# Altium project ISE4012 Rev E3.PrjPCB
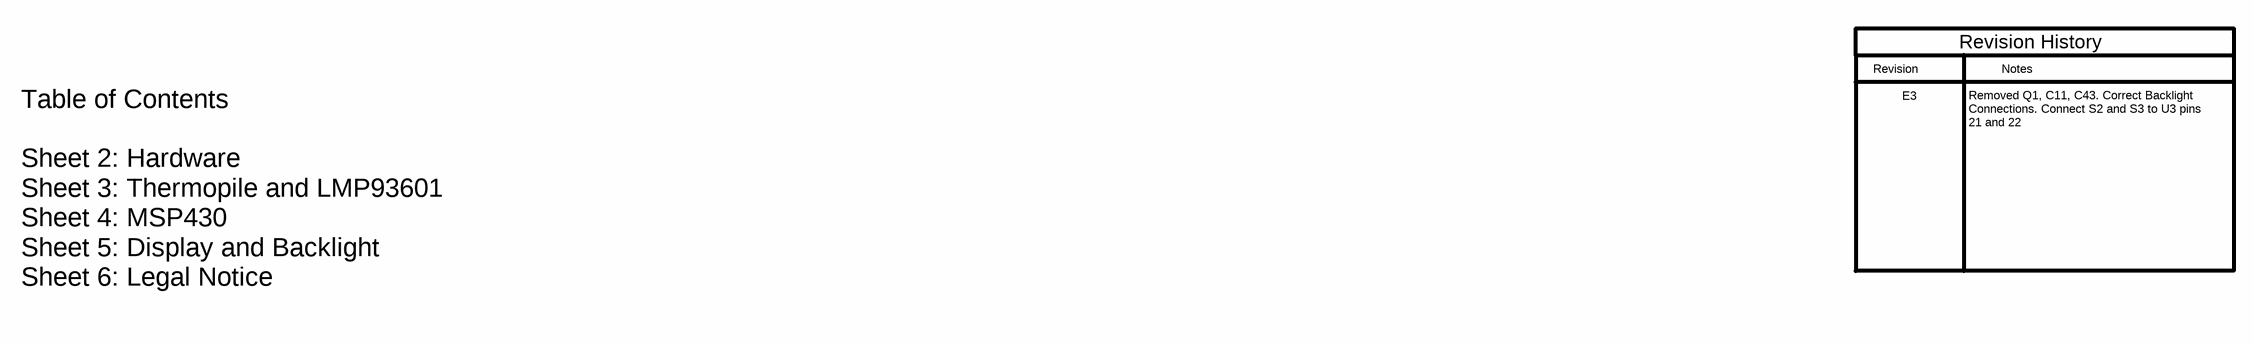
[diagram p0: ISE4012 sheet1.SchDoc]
TechSupport: http://www.ti.com/support; SCH_Rev: E3; PRJ_Title: TIDA-00211 Thermopile Hand Gesture Backlight Controller; PRJ_Number: ISE4012; PRJ_Engineer: M. Knapp; PRJ_Customer: Public Release; PCB_Rev: E3; PCB_Layout: Krypton Solution LLC; CopyrightYear: 2014
6 sheets, 145 parts. Net scope: global (net labels, ports and power ports of the same name join across sheets).
Board file: ISE4012 RevE3.PcbDoc
Sheets:
  ISE4012 sheet1.SchDoc
  ISE4012 sheet2.SchDoc
  ISE4012 sheet3.SchDoc
  ISE4012 sheet4.SchDoc
  ISE4012 sheet5.SchDoc
  ISE4012 Sheet 6.SchDoc

## Sheet ISE4012 sheet1.SchDoc
size 431 x 279 mm; Date: Not shown in title block; ApprovedBy: Not shown in title block; CheckedBy: Not shown in title block; Author: Not shown in title block; CompanyName: Not shown in title block; Engineer: Not shown in title block; Organization: Not shown in title block; Address1: Not shown in title block; Address2: Not shown in title block; Address3: Not shown in title block; Address4: Not shown in title block; DocumentNumber: 1; Revision: Use project parameter SCH_Rev; SheetNumber: 1; SheetTotal: 6; PageSetup: Record=PageOptions|CenterHorizontal=True|CenterVertical=True|PrintScale=1.00|XCorrection=1.00|YCorrection=1.00|PrintKind=0|BorderSize=5000000|LeftOffset=0|BottomOffset=0|Orientation=2|PaperLength=1000|PaperWidth=1000|Scale=100|PaperSource=15|PrintQuality=600|MediaType=1|DitherType=10|PaperKind=Letter|PrintScaleMode=1

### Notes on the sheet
- Revision
- E3
- Notes
- Revision History
- Removed Q1, C11, C43. Correct Backlight Connections. Connect S2 and S3 to U3 pins 21 and 22
- Table of Contents
  Sheet 2: Hardware
  Sheet 3: Thermopile and LMP93601
  Sheet 4: MSP430
  Sheet 5: Display and Backlight
  Sheet 6: Legal Notice

## Sheet ISE4012 sheet2.SchDoc
size 431 x 279 mm; Date: Not shown in title block; ApprovedBy: Not shown in title block; CheckedBy: Not shown in title block; Author: Not shown in title block; CompanyName: Not shown in title block; Engineer: Not shown in title block; Organization: Not shown in title block; Address1: Not shown in title block; Address2: Not shown in title block; Address3: Not shown in title block; Address4: Not shown in title block; DocumentNumber: 2; Revision: Use project parameter SCH_Rev; SheetNumber: 2; SheetTotal: 6; PageSetup: Record=PageOptions|CenterHorizontal=True|CenterVertical=True|PrintScale=1.00|XCorrection=1.00|YCorrection=1.00|PrintKind=0|BorderSize=5000000|LeftOffset=0|BottomOffset=0|Orientation=2|PaperLength=1000|PaperWidth=1000|Scale=100|PaperSource=15|PrintQuality=600|MediaType=1|DitherType=10|PaperKind=Letter|PrintScaleMode=1
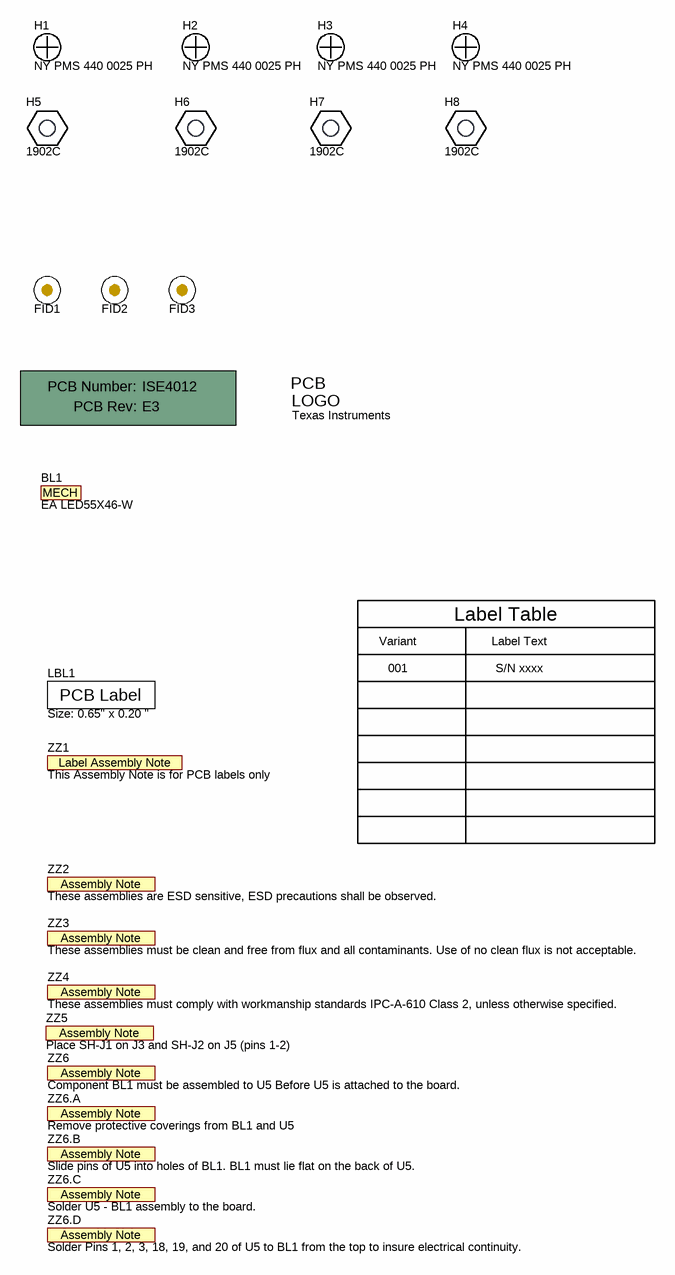
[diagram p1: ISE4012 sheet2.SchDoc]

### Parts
!PCB  Printed Circuit Board  (value not drawn)  (mechanical)
BL1  EA LED55X46-W  (mechanical)
FID1  Fiducial  [Fiducial10-20]  (value not drawn)
FID2  Fiducial  [Fiducial10-20]  (value not drawn)
FID3  Fiducial  [Fiducial10-20]  (value not drawn)
H1  NY PMS 440 0025 PH  [NY PMS 440 0025 PH]
H2  NY PMS 440 0025 PH  [NY PMS 440 0025 PH]
H3  NY PMS 440 0025 PH  [NY PMS 440 0025 PH]
H4  NY PMS 440 0025 PH  [NY PMS 440 0025 PH]
H5  1902C  [Keystone_1902C]
H6  1902C  [Keystone_1902C]
H7  1902C  [Keystone_1902C]
H8  1902C  [Keystone_1902C]
LBL1  Size: 0.65" x 0.20 "  [Label_650x200]
Logo1  Texas Instruments  [TI_Stacked_Overlay_Medium]  (no BOM)
ZZ1  This Assembly Note is for PCB labels only  [AssemblyNoteLabel]  (no BOM)
ZZ2  These assemblies are ESD sensitive, ESD precautions shall be observed.  [AssemblyNote]  (no BOM)
ZZ3  These assemblies must be clean and free from flux and all contaminants. Use of no clean flux is not acceptable.  [AssemblyNote]  (no BOM)
ZZ4  These assemblies must comply with workmanship standards IPC-A-610 Class 2, unless otherwise specified.  [AssemblyNote]  (no BOM)
ZZ5  Place SH-J1 on J3 and SH-J2 on J5 (pins 1-2)  [AssemblyNote]  (no BOM)
ZZ6  Component BL1 must be assembled to U5 Before U5 is attached to the board.  [AssemblyNote]  (no BOM)
ZZ6.A  Remove protective coverings from BL1 and U5  [AssemblyNote]  (no BOM)
ZZ6.B  Slide pins of U5 into holes of BL1. BL1 must lie flat on the back of U5.  [AssemblyNote]  (no BOM)
ZZ6.C  Solder U5 - BL1 assembly to the board.  [AssemblyNote]  (no BOM)
ZZ6.D  Solder Pins 1, 2, 3, 18, 19, and 20 of U5 to BL1 from the top to insure electrical continuity.  [AssemblyNote]  (no BOM)

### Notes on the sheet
- Variant
- Label Table
- Label Text
- 001
- S/N xxxx

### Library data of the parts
!PCB = PCB: Manufacturer: Any; PartNumber: ISE4012; SymbolCreator: a0412235
BL1 = EA LED55X46-W: LED Backlight, White; Manufacturer: Electronic Assembly; SymbolCreator: codlsc
FID1-FID3 = Fiducial: Fiducial mark.  There is nothing to buy or mount.; SymbolCreator: codlsc
H1-H4 = NY PMS 440 0025 PH: Machine Screw, Round, #4-40 x 1/4, Nylon, Philips panhead; Manufacturer: B&F Fastener Supply; CompType: Hardware; SymbolCreator: codlsc; U/M: EA
H5-H8 = 1902C: Standoff, Hex, 0.5"L #4-40 Nylon; Manufacturer: Keystone; CompType: Hardware
LBL1 = THT-14-423-10: Thermal Transfer Printable Labels, 0.650" W x 0.200" H - 10,000 per roll; Manufacturer: Brady; SymbolCreator: a0412235; CompType: Label
Logo1 = TI_Logo: Texas Instrument Corporate Signature; SymbolCreator: a0412235
ZZ1 = AssemblyNoteLabel: SymbolCreator: a0412235
ZZ2-ZZ6 ZZ6.A ZZ6.B ZZ6.C ZZ6.D = AssemblyNote: SymbolCreator: codlsc

## Sheet ISE4012 sheet3.SchDoc
size 431 x 279 mm; Date: Not shown in title block; ApprovedBy: Not shown in title block; CheckedBy: Not shown in title block; Author: Not shown in title block; CompanyName: Not shown in title block; Engineer: Not shown in title block; Organization: Not shown in title block; Address1: Not shown in title block; Address2: Not shown in title block; Address3: Not shown in title block; Address4: Not shown in title block; DocumentNumber: 3; Revision: Use project parameter SCH_Rev; SheetNumber: 3; SheetTotal: 6; PageSetup: Record=PageOptions|CenterHorizontal=True|CenterVertical=True|PrintScale=0.96|XCorrection=1.00|YCorrection=1.00|PrintKind=0|BorderSize=5000000|LeftOffset=0|BottomOffset=0|Orientation=2|PaperLength=4318|PaperWidth=2794|Scale=100|PaperSource=15|PrintQuality=600|MediaType=1|DitherType=10|PaperKind=11x17|PrintScaleMode=1
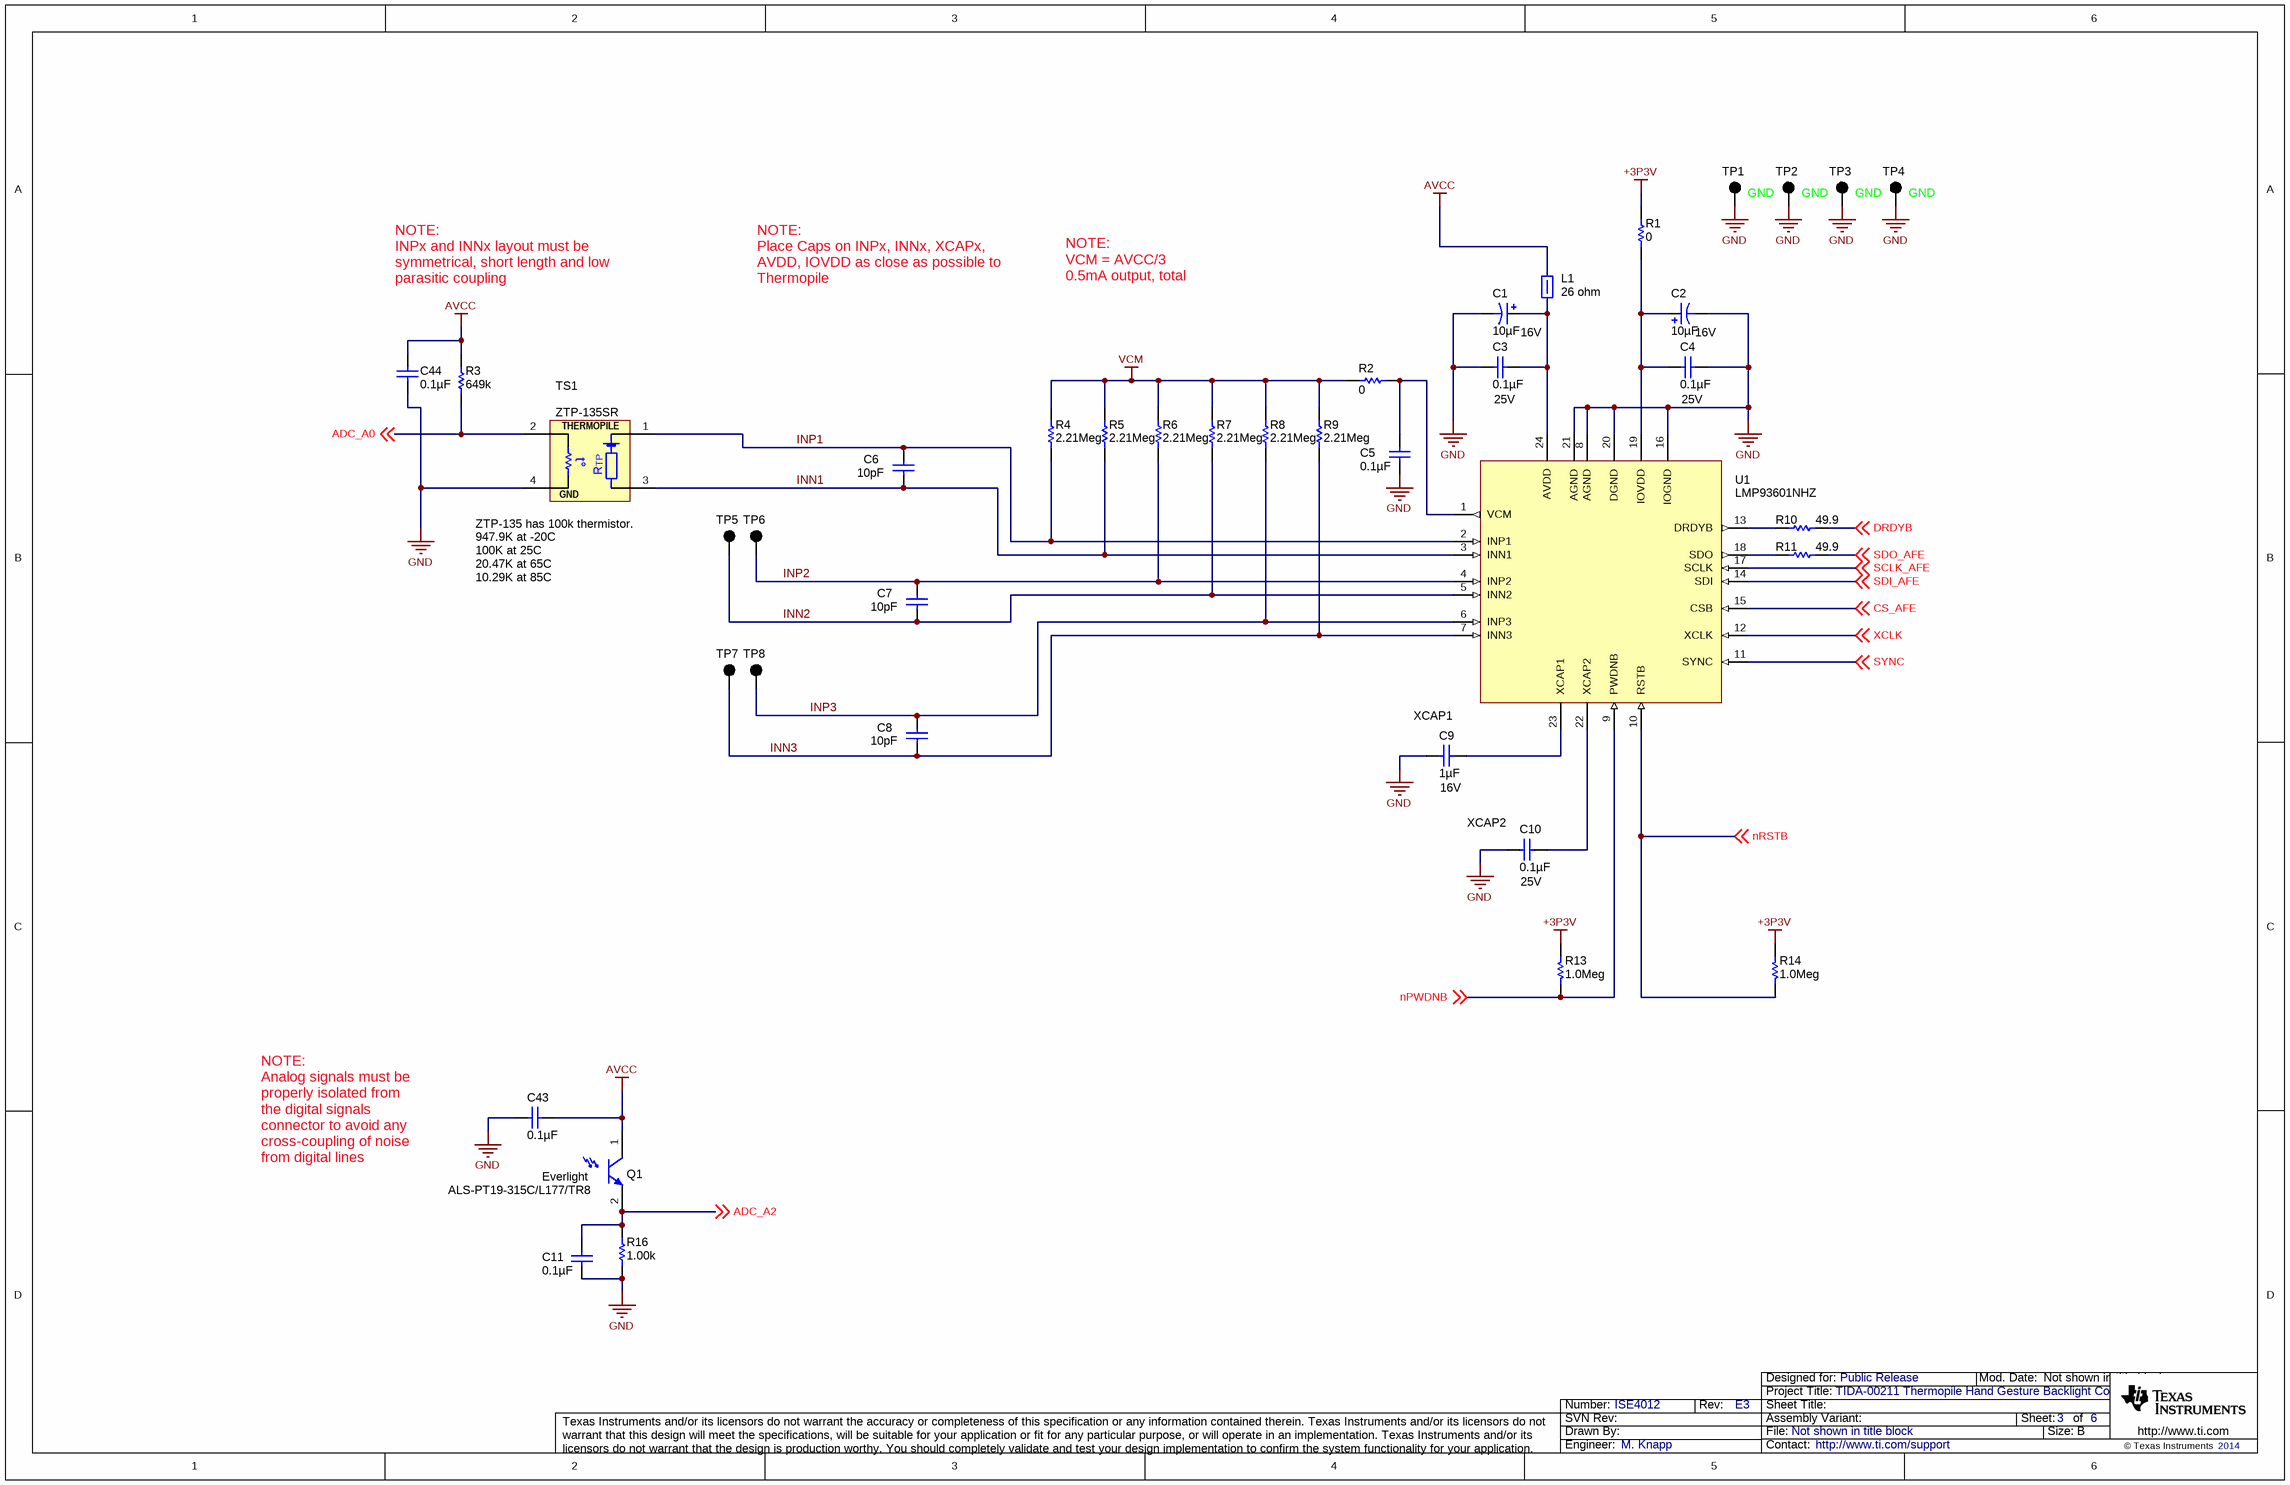
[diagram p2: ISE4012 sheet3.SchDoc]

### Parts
C1  ValueDisplayed: 10µF  Value2: 16V  [3528-21]  (hidden comment: TPSB106K016R0800)
C2  ValueDisplayed: 10µF  Value2: 16V  [3528-21]  (hidden comment: TPSB106K016R0800)
C3  ValueDisplayed: 0.1µF  Value2: 25V  [0603]  (hidden comment: 06033C104JAT2A)
C4  ValueDisplayed: 0.1µF  Value2: 25V  [0603]  (hidden comment: 06033C104JAT2A)
C5  ValueDisplayed: 0.1µF  [0603]  (hidden comment: 06033C104JAT2A)
C6  ValueDisplayed: 10pF  [0603]  (hidden comment: 06033C104JAT2A)
C7  ValueDisplayed: 10pF  [0603]  (hidden comment: 06033C104JAT2A)
C8  ValueDisplayed: 10pF  [0603]  (hidden comment: 06033C104JAT2A)
C9  ValueDisplayed: 1µF  Value2: 16V  [0603]  (hidden comment: C1608X7R1C105K)
C10  ValueDisplayed: 0.1µF  Value2: 25V  [0603]  (hidden comment: 06033C104JAT2A)
C11  ValueDisplayed: 0.1µF  [0603]  (hidden comment: 06033C104JAT2A)
C43  ValueDisplayed: 0.1µF  [0603]  (hidden comment: 06033C104JAT2A)
C44  ValueDisplayed: 0.1µF  [0603]  (hidden comment: 06033C104JAT2A)
L1  value 26 ohm  [0603]  (hidden comment: BLM18SG260TN1D)
Q1  Manufacturer: Everlight  [ALS-PT19-315C-L177-TR8]  (hidden comment: ALS-PT19-315C/L177/TR8)
R1  value 0  [0603]  (hidden comment: CRCW06030000Z0EA)
R2  value 0  [0603]  (hidden comment: CRCW06030000Z0EA)
R3  value 649k  [0603]  (hidden comment: CRCW0603649KFKEA)
R4  value 2.21Meg  [0603]  (hidden comment: RC0603FR-072M21L)
R5  value 2.21Meg  [0603]  (hidden comment: RC0603FR-072M21L)
R6  value 2.21Meg  [0603]  (hidden comment: RC0603FR-072M21L)
R7  value 2.21Meg  [0603]  (hidden comment: RC0603FR-072M21L)
R8  value 2.21Meg  [0603]  (hidden comment: RC0603FR-072M21L)
R9  value 2.21Meg  [0603]  (hidden comment: RC0603FR-072M21L)
R10  value 49.9  [0603]  (hidden comment: CRCW060349R9FKEA)
R11  value 49.9  [0603]  (hidden comment: CRCW060349R9FKEA)
R13  value 1.0Meg  [0603]  (hidden comment: CRCW06031M00JNEA)
R14  value 1.0Meg  [0603]  (hidden comment: CRCW06031M00JNEA)
R16  value 1.00k  [0603]  (hidden comment: CRCW06031K00FKEA)
TP1  5000  [Keystone5000]  (value not drawn)
TP2  5000  [Keystone5000]  (value not drawn)
TP3  5000  [Keystone5000]  (value not drawn)
TP4  5000  [Keystone5000]  (value not drawn)
TP5  5001  [Keystone5001]  (value not drawn)
TP6  5001  [Keystone5001]  (value not drawn)
TP7  5001  [Keystone5001]  (value not drawn)
TP8  5001  [Keystone5001]  (value not drawn)
TS1  ZTP-135SR  [TO-46]
U1  LMP93601NHZ  [NHZ0024B]

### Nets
+3P3V: R1.2 R13.2 R14.2
AVCC: C43.1 C44.1 L1.2 Q1.1(C) R3.2
GND: C1.2(-) C2.2(-) C3.2 C4.1 C5.2 C9.2 C10.2 C11.2 C43.2 C44.2 R16.1 TP1.1 TP2.1 TP3.1 TP4.1 TS1.4(IN) U1.8(AGND) U1.16(IOGND) U1.20(DGND) U1.21(AGND)
VCM: R2.1 R4.2 R5.2 R6.2 R7.2 R8.2 R9.2
ADC_A0: R3.1 TS1.2(IN) ; off-sheet ADC_A0
ADC_A2: C11.1 Q1.2(E) R16.2 ; off-sheet ADC_A2
CS_AFE: U1.15(CSB) ; off-sheet CS_AFE
DRDYB: R10.2 ; off-sheet DRDYB
INN1: C6.2 R5.1 TS1.3(OUT) U1.3(INN1)
INN2: C7.2 R7.1 TP5.1 U1.5(INN2)
INN3: C8.2 R9.1 TP7.1 U1.7(INN3)
INP1: C6.1 R4.1 TS1.1(OUT) U1.2(INP1)
INP2: C7.1 R6.1 TP6.1 U1.4(INP2)
INP3: C8.1 R8.1 TP8.1 U1.6(INP3)
nPWDNB: R13.1 U1.9(PWDNB) ; off-sheet nPWDNB
nRSTB: R14.1 U1.10(RSTB) ; off-sheet nRSTB
SCLK_AFE: U1.17(SCLK) ; off-sheet SCLK_AFE
SDI_AFE: U1.14(SDI) ; off-sheet SDI_AFE
SDO_AFE: R11.2 ; off-sheet SDO_AFE
SYNC: U1.11(SYNC) ; off-sheet SYNC
XCLK: U1.12(XCLK) ; off-sheet XCLK
NetC1_1: C1.1(+) C3.1 L1.1 U1.24(AVDD)
NetC2_1: C2.1(+) C4.2 R1.1 U1.19(IOVDD)
NetC5_1: C5.1 R2.2 U1.1(VCM)
NetC9_1: C9.1 U1.23(XCAP1)
NetC10_1: C10.1 U1.22(XCAP2)
NetR10_1: R10.1 U1.13(DRDYB)
NetR11_1: R11.1 U1.18(SDO)

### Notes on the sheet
- GND
- (near TP4) GND
- NOTE:
  INPx and INNx layout must be symmetrical, short length and low parasitic coupling
- NOTE:
  Place Caps on INPx, INNx, XCAPx, AVDD, IOVDD as close as possible to Thermopile
- NOTE:
  VCM = AVCC/3
  0.5mA output, total
- (near TS1) ZTP-135 has 100k thermistor.
  947.9K at -20C
  100K at 25C
  20.47K at 65C
  10.29K at 85C
- XCAP1
- (near C10) XCAP2
- NOTE:
  Analog signals must be properly isolated from the digital signals connector to avoid any cross-coupling of noise from digital lines

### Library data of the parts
C1 C2 = TPSB106K016R0800: CAP, TANT, 10uF, 16V, +/-10%, 0.8 ohm, 3528-21 SMD; Manufacturer: AVX; Polarized: Y; CompType: Capacitor; U/M: EA; Cap_F: 0.00001; Tolerance_%: 10; Value1: 0.8 ohm; VDC_V: 16; ESR_Ohm: 0.8; IRMS_A: 0.293; TaMin_C: -55; TaMax_C: 125; Cap_Case: B
C3-C5 C10 C11 C43 C44 = 06033C104JAT2A: CAP, CERM, 0.1uF, 25V, +/-5%, X7R, 0603; Manufacturer: AVX; Polarized: N; CompType: Capacitor; U/M: EA; Cap_F: 0.0000001; Tolerance_%: 5; ESR_Ohm: 0.05; Value1: 0.05 ohm; VDC_V: 25; TaMin_C: -55; TaMax_C: 125
C6-C8 = 06033C104JAT2A: CAP, CERM, 0.1uF, 25V, +/-5%, X7R, 0603; Manufacturer: AVX; ESR_Ohm: 0.05; Polarized: N; TaMax_C: 125; TaMin_C: -55; Tolerance_%: 5; VDC_V: 25; Cap_F: 0.0000001; CompType: Capacitor; U/M: EA; Value1: 0.05 ohm
C9 = C1608X7R1C105K: CAP, CERM, 1uF, 16V, +/-10%, X7R, 0603; Manufacturer: TDK; Polarized: N; CompType: Capacitor; U/M: EA; Cap_F: 0.000001; Tolerance_%: 10; ESR_Ohm: 0.0057; Value1: 0.0057 ohm; VDC_V: 16; TaMin_C: -55; TaMax_C: 125
L1 = BLM18SG260TN1D: 6A Ferrite Bead, 26 ohm @ 100MHz, SMD; Manufacturer: MuRata; Imax_A: 6; DCR_ohm: 0.007; Value1: 0.007 ohm; ZTyp@100MHz_Ohm: 26; U/M: EA
Q1 = ALS-PT19-315C/L177/TR8: AMBIENT LIGHT SENSOR, SMD; Symbol Creator: a0411947
R1 R2 = CRCW06030000Z0EA: RES, 0 ohm, 5%, 0.1W, 0603; Manufacturer: Vishay-Dale; CompType: Resistor; Value_Code: 0000; Tolerance_%: 5; Power_W: 0.1; VDC_V: 75; TempCo: 200 ppm/C; EIA_Code: E24; U/M: EA
R3 = CRCW0603649KFKEA: RES, 649k ohm, 1%, 0.1W, 0603; Manufacturer: Vishay-Dale; CompType: Resistor; Res_ohm: 649000; Tolerance_%: 1; Power_W: 0.1; VDC_V: 75; TempCo: 100 ppm/C; EIA_Code: E96; U/M: EA
R4-R9 = RC0603FR-072M21L: RES, 2.21Meg ohm, 1%, 0.1W, 0603; Manufacturer: Yageo America; CompType: Resistor; Res_ohm: 2210000; Value_Code: 2M21; Tolerance_%: 1; Power_W: 0.1; VDC_V: 150; TempCo: 200 ppm/C; EIA_Code: E96; U/M: EA
R10 R11 = CRCW060349R9FKEA: RES, 49.9 ohm, 1%, 0.1W, 0603; Manufacturer: Vishay-Dale; CompType: Resistor; Value_Code: 49R9; Tolerance_%: 1; Power_W: 0.1; VDC_V: 75; TempCo: 100 ppm/C; EIA_Code: E96; U/M: EA
R13 R14 = CRCW06031M00JNEA: RES, 1.0Meg ohm, 5%, 0.1W, 0603; Manufacturer: Vishay-Dale; CompType: Resistor; Tolerance_%: 5; VDC_V: 75; Power_W: 0.1; Res_ohm: 1000000; Value_Code: 1M00; TempCo_ppm/C: 200; EIA_Code: E24; U/M: EA
R16 = CRCW06031K00FKEA: RES, 1.00k ohm, 1%, 0.1W, 0603; Manufacturer: Vishay-Dale; CompType: Resistor; Res_ohm: 1000; Value_Code: 1k00; Tolerance_%: 1; Power_W: 0.1; VDC_V: 75; TempCo: 100 ppm/C; EIA_Code: E96; U/M: EA
TP1-TP8 = 5001: Test Point, Miniature, Black, TH; Manufacturer: Keystone; CompType: Test Point Loop; U/M: EA
TS1 = ZTP-135SR: Thermopile IR Sensor, TO-46; Manufacturer: Amphenol RF; SymbolCreator: a0799628
U1 = LMP93601NHZ: 16-bit analog-front-end for thermopile occupancy detector arrays, NHZ0024B; Alternate Manufacturer: None; Manufacturer: Texas Instruments; SymbolCreator: a0412235; CompType: IC; U/M: EA

## Sheet ISE4012 sheet4.SchDoc
size 431 x 279 mm; Date: Not shown in title block; ApprovedBy: Not shown in title block; CheckedBy: Not shown in title block; Author: Not shown in title block; CompanyName: Not shown in title block; Engineer: Not shown in title block; Organization: Not shown in title block; Address1: Not shown in title block; Address2: Not shown in title block; Address3: Not shown in title block; Address4: Not shown in title block; DocumentNumber: 4; Revision: Use project parameter SCH_Rev; SheetNumber: 4; SheetTotal: 6; PageSetup: Record=PageOptions|CenterHorizontal=True|CenterVertical=True|PrintScale=0.96|XCorrection=1.00|YCorrection=1.00|PrintKind=0|BorderSize=5000000|LeftOffset=0|BottomOffset=0|Orientation=2|PaperLength=4318|PaperWidth=2794|Scale=100|PaperSource=15|PrintQuality=600|MediaType=1|DitherType=10|PaperKind=11x17|PrintScaleMode=1
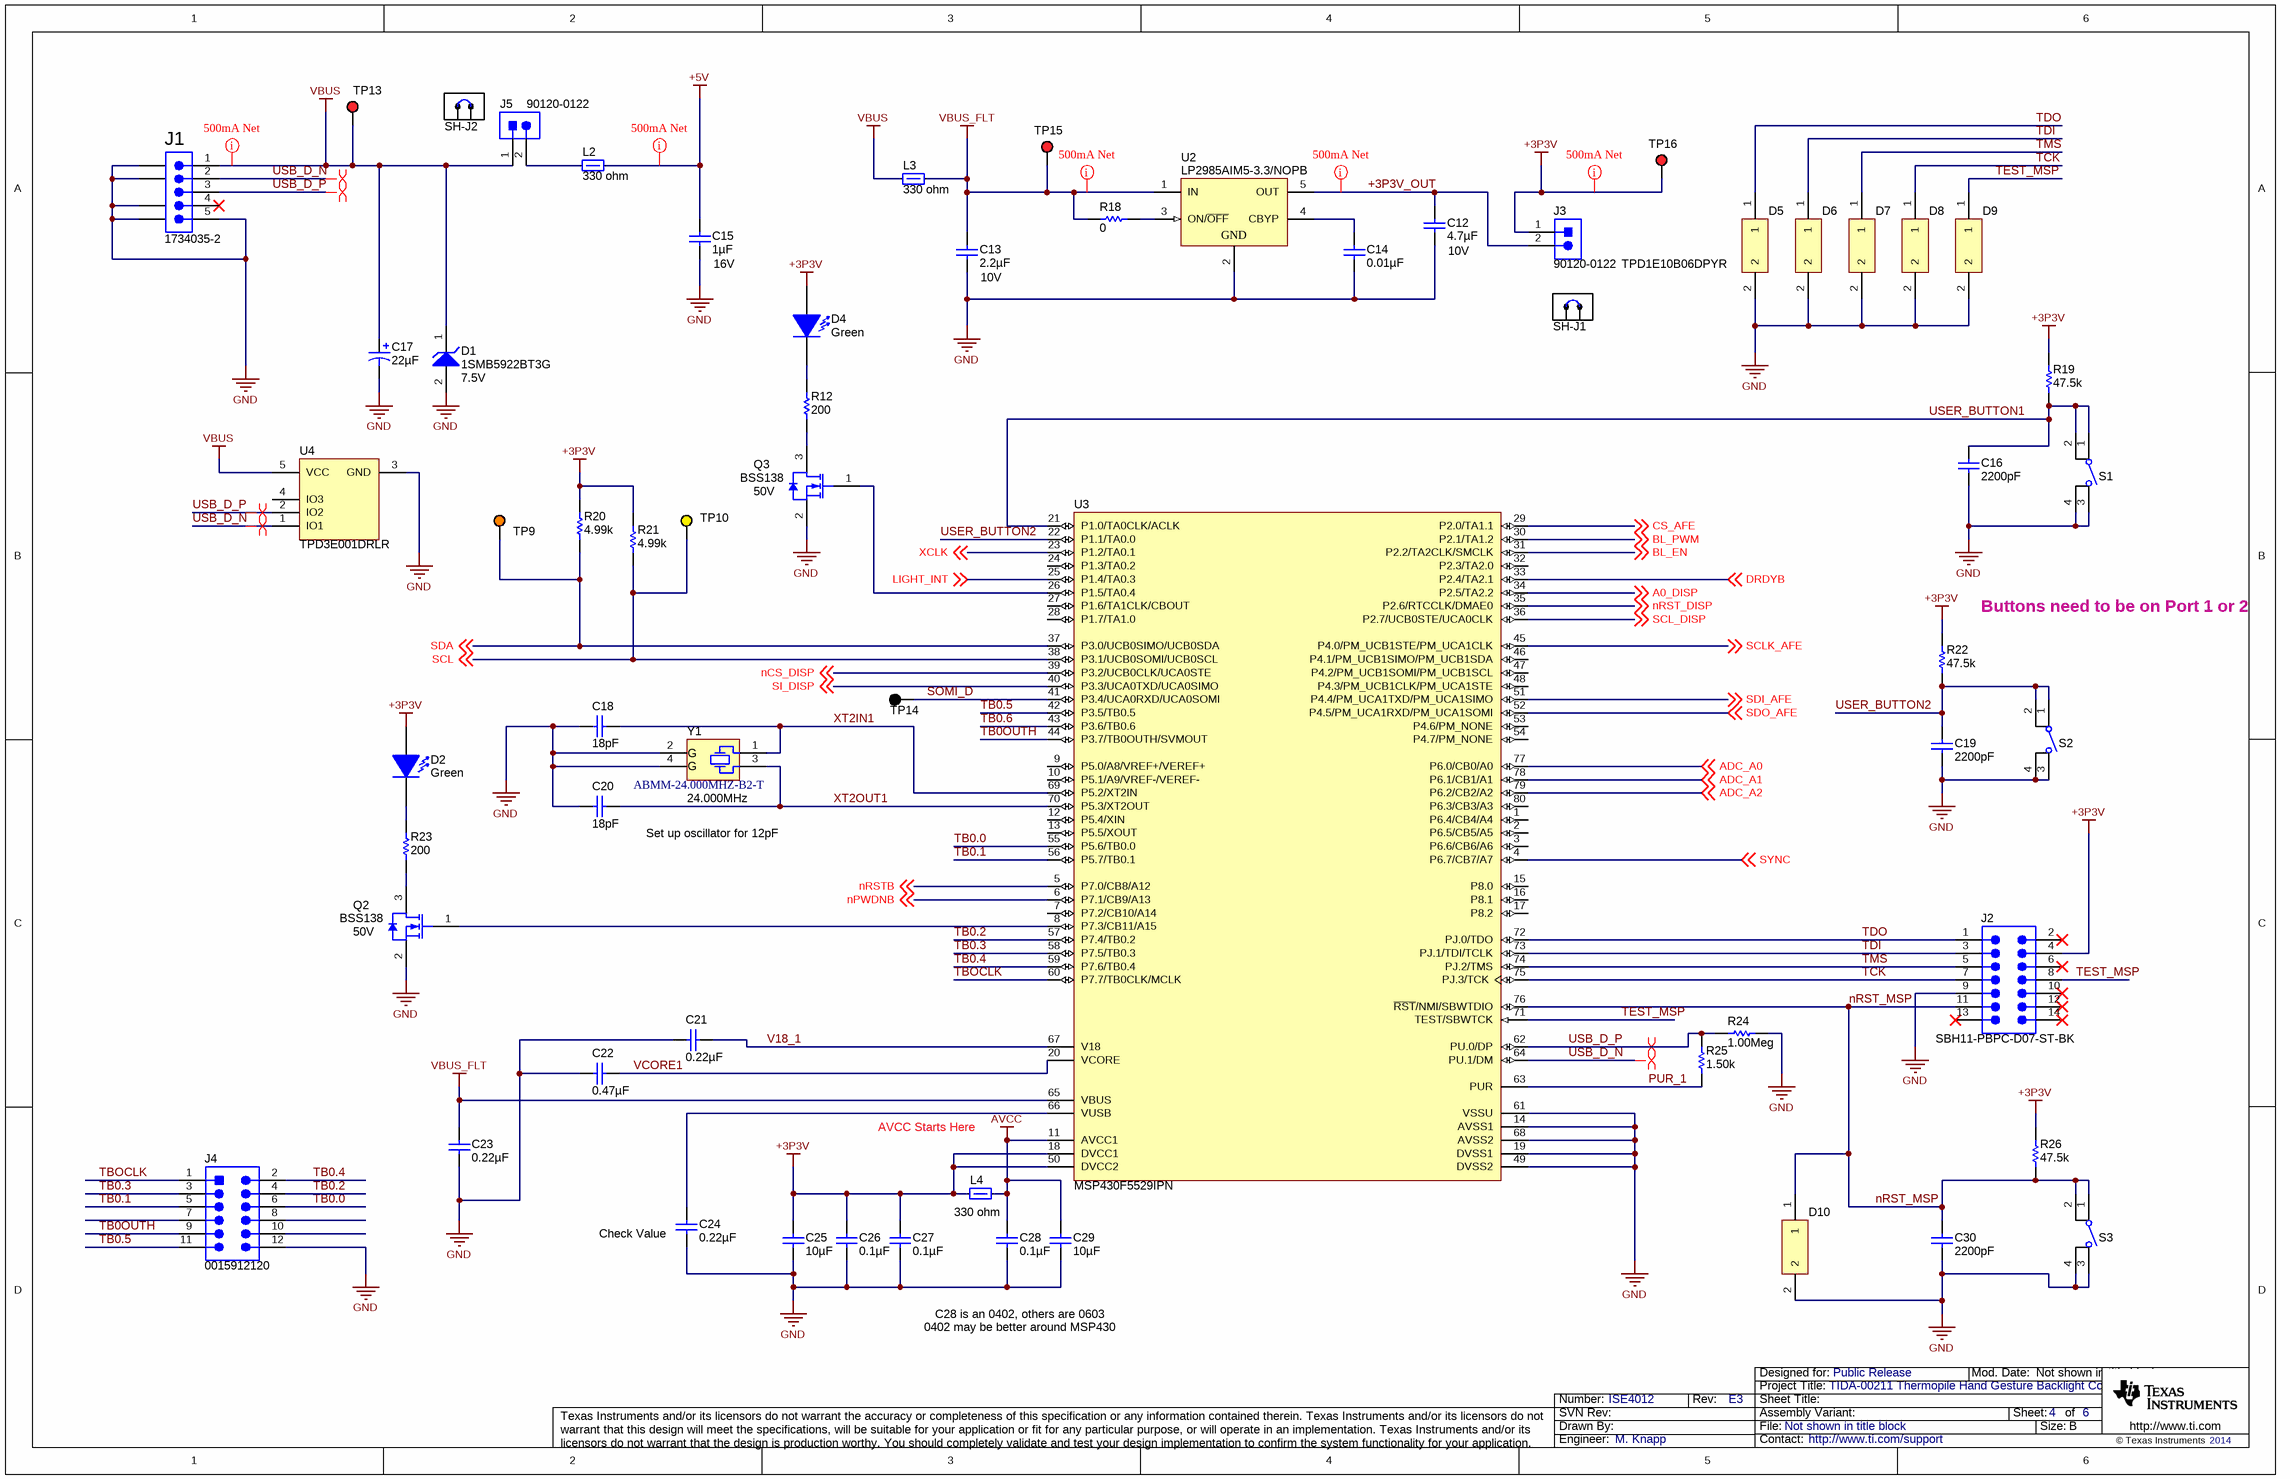
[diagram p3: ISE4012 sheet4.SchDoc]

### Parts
C12  ValueDisplayed: 4.7µF  Value2: 10V  [0805_HV]  (hidden comment: 0805ZD475KAT2A)
C13  ValueDisplayed: 2.2µF  Value2: 10V  [0805_HV]  (hidden comment: C0805C225K8PACTU)
C14  ValueDisplayed: 0.01µF  [0402]  (hidden comment: GRM155R71C103KA01D)
C15  ValueDisplayed: 1µF  Value2: 16V  [0603]  (hidden comment: C1608X7R1C105K)
C16  ValueDisplayed: 2200pF  [0603]  (hidden comment: 06031C222JAT2A)
C17  ValueDisplayed: 22µF  [CAPSMT_62_E55]  (hidden comment: EEE-1AA220WR)
C18  ValueDisplayed: 18pF  [0603]  (hidden comment: 06035A180JAT2A)
C19  ValueDisplayed: 2200pF  [0603]  (hidden comment: 06031C222JAT2A)
C20  ValueDisplayed: 18pF  [0603]  (hidden comment: 06035A180JAT2A)
C21  ValueDisplayed: 0.22µF  [0402]  (hidden comment: GRM155R61A224KE19D)
C22  ValueDisplayed: 0.47µF  [0402]  (hidden comment: GRM155R61A474KE15D)
C23  ValueDisplayed: 0.22µF  [0402]  (hidden comment: GRM155R61A224KE19D)
C24  ValueDisplayed: 0.22µF  [0402]  (hidden comment: GRM155R61A224KE19D)
C25  ValueDisplayed: 10µF  [0805_HV]  (hidden comment: C0805C106K8PACTU)
C26  ValueDisplayed: 0.1µF  [0603]  (hidden comment: 06033C104JAT2A)
C27  ValueDisplayed: 0.1µF  [0603]  (hidden comment: 06033C104JAT2A)
C28  ValueDisplayed: 0.1µF  [0402]  (hidden comment: GRM155R61C104KA88D)
C29  ValueDisplayed: 10µF  [0805_HV]  (hidden comment: C0805C106K8PACTU)
C30  ValueDisplayed: 2200pF  [0603]  (hidden comment: 06031C222JAT2A)
D1  1SMB5922BT3G  value 7.5V  [SMB]
D2  value Green  [LED_LTST-C171]  (hidden comment: LTST-C190GKT)
D4  value Green  [LED_LTST-C171]  (hidden comment: LTST-C190GKT)
D5  TPD1E10B06DPYR  [DPY0002A_N]
D6  TPD1E10B06DPYR  [DPY0002A_N]  (value not drawn)
D7  TPD1E10B06DPYR  [DPY0002A_N]  (value not drawn)
D8  TPD1E10B06DPYR  [DPY0002A_N]  (value not drawn)
D9  TPD1E10B06DPYR  [DPY0002A_N]  (value not drawn)
D10  TPD1E10B06DPYR  [DPY0002A_N]  (value not drawn)
J1  1734035-2  [CONN_USB-Mini-B-1734035-2]
J2  SBH11-PBPC-D07-ST-BK  [CONN_SBH11-PBPC-D07-ST-BK]
J3  90120-0122  [CONN_90120-0122]
J4  0015912120  [MOLEX_0015912120]
J5  90120-0122  [CONN_90120-0122]
L2  value 330 ohm  [0603]  (hidden comment: BLM18SG331TN1D)
L3  value 330 ohm  [0603]  (hidden comment: BLM18SG331TN1D)
L4  value 330 ohm  [0603]  (hidden comment: BLM18SG331TN1D)
Q2  BSS138  value 50V  [SOT-23]
Q3  BSS138  value 50V  [SOT-23]
R12  value 200  [0603]  (hidden comment: CRCW0603200RJNEA)
R18  value 0  [0402]  (hidden comment: CRCW04020000Z0ED)
R19  value 47.5k  [0603]  (hidden comment: CRCW060347K5FKEA)
R20  value 4.99k  [0402]  (hidden comment: CRCW04024K99FKED)
R21  value 4.99k  [0402]  (hidden comment: CRCW04024K99FKED)
R22  value 47.5k  [0603]  (hidden comment: CRCW060347K5FKEA)
R23  value 200  [0603]  (hidden comment: CRCW0603200RJNEA)
R24  value 1.00Meg  [0402L]  (hidden comment: CRCW04021M00FKED)
R25  value 1.50k  [0402L]  (hidden comment: CRCW04021K50FKED)
R26  value 47.5k  [0603]  (hidden comment: CRCW060347K5FKEA)
S1  4-1437565-1  [SW_FSM4JSMA]  (value not drawn)
S2  4-1437565-1  [SW_FSM4JSMA]  (value not drawn)
S3  4-1437565-1  [SW_FSM4JSMA]  (value not drawn)
SH-J1  2SN-BK-G  [2SN-BK-G]  (value not drawn)
SH-J2  2SN-BK-G  [2SN-BK-G]  (value not drawn)
TP9  5003  [Keystone5003]  (value not drawn)
TP10  5004  [Keystone5004]  (value not drawn)
TP13  5000  [Keystone5000]  (value not drawn)
TP14  5000  [Keystone5000]  (value not drawn)
TP15  5000  [Keystone5000]  (value not drawn)
TP16  5000  [Keystone5000]  (value not drawn)
U2  LP2985AIM5-3.3/NOPB  [MF05A_N]
U3  MSP430F5529IPN  [PN0080A_N]
U4  TPD3E001DRLR  [DRL0005A]
Y1  ABMM-24.000MHZ-B2-T  Frequency: 24.000MHz  [Abracon_ABMM]

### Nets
+3P3V: C25.1 C26.1 C27.1 D2.1(A) D4.1(A) J2.4 J3.1 L4.1 R19.2 R20.2 R21.2 R22.2 R26.2 TP16.1 U3.18(DVCC1) U3.50(DVCC2)
+5V: C15.1 L2.2
AVCC: C28.1 C29.1 L4.2 U3.11(AVCC1)
GND: C12.2 C13.2 C14.2 C15.2 C16.2 C17.2(-) C18.2 C19.2 C20.2 C21.2 C22.2 C23.2 C24.2 C25.2 C26.2 C27.2 C28.2 C29.2 C30.2 D1.2(A) D5.2 D6.2 D7.2 D8.2 D9.2 D10.2 J1.5 J1.6(GND) J1.7(GND) J1.8(GND) J1.9(GND) J2.9 J4.12 Q2.2(S) Q3.2(S) R24.2 S1.3 S1.4 S2.3 S2.4 S3.3 S3.4 U2.2(GND) U3.14(AVSS1) U3.19(DVSS1) U3.49(DVSS2) U3.61(VSSU) U3.68(AVSS2) U4.3(GND) Y1.2(GND) Y1.4(GND)
VBUS: C17.1(+) D1.1(K) J1.1 J5.1 L3.1 TP13.1 U4.5(VCC)
VBUS_FLT: C13.1 C23.1 L3.2 R18.2 TP15.1 U2.1(IN) U3.65(VBUS)
+3P3V_OUT: C12.1 J3.2 U2.5(OUT)
A0_DISP: U3.34(P2.5/TA2.2) ; off-sheet A0_DISP
ADC_A0: U3.77(P6.0/CB0/A0) ; off-sheet ADC_A0
ADC_A1: U3.78(P6.1/CB1/A1) ; off-sheet ADC_A1
ADC_A2: U3.79(P6.2/CB2/A2) ; off-sheet ADC_A2
BL_EN: U3.31(P2.2/TA2CLK/SMCLK) ; off-sheet BL_EN
BL_PWM: U3.30(P2.1/TA1.2) ; off-sheet BL_PWM
CS_AFE: U3.29(P2.0/TA1.1) ; off-sheet CS_AFE
DRDYB: U3.33(P2.4/TA2.1) ; off-sheet DRDYB
LIGHT_INT: U3.25(P1.4/TA0.3) ; off-sheet LIGHT_INT
nCS_DISP: U3.39(P3.2/UCB0CLK/UCA0STE) ; off-sheet nCS_DISP
nPWDNB: U3.6(P7.1/CB9/A13) ; off-sheet nPWDNB
nRST_DISP: U3.35(P2.6/RTCCLK/DMAE0) ; off-sheet nRST_DISP
nRST_MSP: C30.1 D10.1 J2.11 R26.1 S3.1 S3.2 U3.76(~{RST}/NMI/SBWTDIO)
nRSTB: U3.5(P7.0/CB8/A12) ; off-sheet nRSTB
PUR_1: R25.1 U3.63(PUR)
SCL: R21.1 TP10.1 U3.38(P3.1/UCB0SOMI/UCB0SCL) ; off-sheet SCL
SCL_DISP: U3.36(P2.7/UCB0STE/UCA0CLK) ; off-sheet SCL_DISP
SCLK_AFE: U3.45(P4.0/PM_UCB1STE/PM_UCA1CLK) ; off-sheet SCLK_AFE
SDA: R20.1 TP9.1 U3.37(P3.0/UCB0SIMO/UCB0SDA) ; off-sheet SDA
SDI_AFE: U3.51(P4.4/PM_UCA1TXD/PM_UCA1SIMO) ; off-sheet SDI_AFE
SDO_AFE: U3.52(P4.5/PM_UCA1RXD/PM_UCA1SOMI) ; off-sheet SDO_AFE
SI_DISP: U3.40(P3.3/UCA0TXD/UCA0SIMO) ; off-sheet SI_DISP
SOMI_D: TP14.1 U3.41(P3.4/UCA0RXD/UCA0SOMI)
SYNC: U3.4(P6.7/CB7/A7) ; off-sheet SYNC
TB0.0: J4.6 U3.55(P5.6/TB0.0)
TB0.1: J4.5 U3.56(P5.7/TB0.1)
TB0.2: J4.4 U3.57(P7.4/TB0.2)
TB0.3: J4.3 U3.58(P7.5/TB0.3)
TB0.4: J4.2 U3.59(P7.6/TB0.4)
TB0.5: J4.11 U3.42(P3.5/TB0.5)
TB0.6: U3.43(P3.6/TB0.6)
TB0OUTH: J4.9 U3.44(P3.7/TB0OUTH/SVMOUT)
TBOCLK: J4.1 U3.60(P7.7/TB0CLK/MCLK)
TCK: D8.1 J2.7 U3.75(PJ.3/TCK)
TDI: D6.1 J2.3 U3.73(PJ.1/TDI/TCLK)
TDO: D5.1 J2.1 U3.72(PJ.0/TDO)
TEST_MSP: D9.1 J2.8 U3.71(TEST/SBWTCK)
TMS: D7.1 J2.5 U3.74(PJ.2/TMS)
USB_D_N: J1.2 U3.64(PU.1/DM) U4.1(IO1)
USB_D_P: J1.3 R24.1 R25.2 U3.62(PU.0/DP) U4.2(IO2)
USER_BUTTON1: C16.1 R19.1 S1.1 S1.2 U3.21(P1.0/TA0CLK/ACLK)
USER_BUTTON2: C19.1 R22.1 S2.1 S2.2 U3.22(P1.1/TA0.0)
V18_1: C21.1 U3.67(V18)
VCORE1: C22.1 U3.20(VCORE)
XCLK: U3.23(P1.2/TA0.1) ; off-sheet XCLK
XT2IN1: C18.1 U3.69(P5.2/XT2IN) Y1.1
XT2OUT1: C20.1 U3.70(P5.3/XT2OUT) Y1.3
NetC14_1: C14.1 U2.4(CBYP)
NetC24_1: C24.1 U3.66(VUSB)
NetD2_2: D2.2(K) R23.2
NetD4_2: D4.2(K) R12.2
NetJ5_2: J5.2 L2.1
NetQ2_1: Q2.1(G) U3.8(P7.3/CB11/A15)
NetQ2_3: Q2.3(D) R23.1
NetQ3_1: Q3.1(G) U3.26(P1.5/TA0.4)
NetQ3_3: Q3.3(D) R12.1
NetR18_1: R18.1 U2.3(ON/~{OFF})

Not connected (* = marked no-connect by the designer): J1 4*; J2 2* 6* 10* 12* 13* 14*; J4 7 8 10; U3 1(P6.4/CB4/A4) 2(P6.5/CB5/A5) 3(P6.6/CB6/A6) 7(P7.2/CB10/A14) 9(P5.0/A8/VREF+/VEREF+) 10(P5.1/A9/VREF-/VEREF-) 12(P5.4/XIN) 13(P5.5/XOUT) 15(P8.0) 16(P8.1) 17(P8.2) 24(P1.3/TA0.2) 27(P1.6/TA1CLK/CBOUT) 28(P1.7/TA1.0) 32(P2.3/TA2.0) 46(P4.1/PM_UCB1SIMO/PM_UCB1SDA) 47(P4.2/PM_UCB1SOMI/PM_UCB1SCL) 48(P4.3/PM_UCB1CLK/PM_UCA1STE) 53(P4.6/PM_NONE) 54(P4.7/PM_NONE) 80(P6.3/CB3/A3); U4 4(IO3)

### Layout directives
rule Width Constraint [Pref Width = 25mil    Min Width = 5mil    Max Width = 100mil]: +3P3V, +3P3V_OUT, +5V, VBUS, VBUS_FLT
differential pair: USB_D_N, USB_D_P

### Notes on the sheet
- (near R22) Buttons need to be on Port 1 or 2
- (near C20) Set up oscillator for 12pF
- AVCC Starts Here
- (near C24) Check Value
- 0402 may be better around MSP430
- C28 is an 0402, others are 0603

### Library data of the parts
C12 = 0805ZD475KAT2A: CAP, CERM, 4.7uF, 10V, +/-10%, X5R, 0805; Manufacturer: AVX; Polarized: N; CompType: Capacitor; U/M: EA; Cap_F: 0.0000047; Tolerance_%: 10; ESR_Ohm: 0.007; Value1: 0.007 ohm; TaMin_C: -55; TaMax_C: 85; Cap_Case: 0805
C13 = C0805C225K8PACTU: CAP, CERM, 2.2uF, 10V, +/-10%, X5R, 0805; Manufacturer: Kemet; Polarized: N; CompType: Capacitor; U/M: EA; Cap_F: 0.0000022; Tolerance_%: 10; ESR_Ohm: 0.006; Value1: 0.006 ohm; IRMS_A: 7.32; TaMin_C: -55; TaMax_C: 85; Cap_Case: 0805
C14 = GRM155R71C103KA01D: CAP, CERM, 0.01uF, 16V, +/-10%, X7R, 0402; Manufacturer: MuRata; Polarized: N; CompType: Capacitor; U/M: EA; Cap_F: 0.00000001; Tolerance_%: 10; Value1: Unknown; VDC_V: 16; TaMin_C: -55; TaMax_C: 125
C15 = C1608X7R1C105K: as C9 on sheet ISE4012 sheet3
C16 C19 C30 = 06031C222JAT2A: CAP, CERM, 2200pF, 100V, +/-5%, X7R, 0603; Manufacturer: AVX; Polarized: N; CompType: Capacitor; U/M: EA; Cap_F: 0.0000000022; Tolerance_%: 5; ESR_Ohm: 0.192; Value1: 0.192 ohm; VDC_V: 100; TaMin_C: -55; TaMax_C: 125
C17 = EMVE100ADA220ME55G: CAP ALUM 22UF 10V 20% SMD; Manufacturer: Panasonic - ECG; Polarized: Y; CompType: Capacitor; U/M: EA; Cap_F: 0.000022; Tolerance_%: 20; VDC_V: 10; IRMS_A: 0.03; TaMin_C: -40; TaMax_C: 105; Cap_Case: E55
C18 C20 = 06035A180JAT2A: CAP, CERM, 18pF, 50V, +/-5%, C0G/NP0, 0603; Manufacturer: AVX; Polarized: N; CompType: Capacitor; U/M: EA; Cap_F: 0.000000000018; Tolerance_%: 5; ESR_Ohm: 0.289; Value1: 0.289 ohm; VDC_V: 50; TaMin_C: -55; TaMax_C: 125
C21 C23 C24 = GRM155R61A224KE19D: CAP, CERM, 0.22uF, 10V, +/-10%, X5R, 0402; Manufacturer: MuRata; Polarized: N; CompType: Capacitor; U/M: EA; Cap_F: 0.00000022; Tolerance_%: 10; Value1: Unknown; TaMin_C: -55; TaMax_C: 85
C22 = GRM155R61A474KE15D: CAP, CERM, 0.47uF, 10V, +/-10%, X5R, 0402; Manufacturer: MuRata; Polarized: N; CompType: Capacitor; U/M: EA; Cap_F: 0.00000047; Tolerance_%: 10; Value1: Unknown; TaMin_C: -55; TaMax_C: 85
C25 C29 = C0805C106K8PACTU: CAP, CERM, 10uF, 10V, +/-10%, X5R, 0805; Manufacturer: Kemet; Polarized: N; CompType: Capacitor; U/M: EA; Cap_F: 0.00001; Tolerance_%: 10; ESR_Ohm: 0.003; Value1: 0.003 ohm; IRMS_A: 11.43; TaMin_C: -55; TaMax_C: 85; Cap_Case: 0805
C26 C27 = 06033C104JAT2A: as C3 on sheet ISE4012 sheet3
C28 = GRM155R61C104KA88D: CAP, CERM, 0.1uF, 16V, +/-10%, X5R, 0402; Manufacturer: MuRata; Polarized: N; CompType: Capacitor; U/M: EA; Cap_F: 0.0000001; Tolerance_%: 10; Value1: Unknown; VDC_V: 16; TaMin_C: -55; TaMax_C: 85
D1 = 1SMB5922BT3G: Diode, Zener, 7.5V, 550mW, SMB; Manufacturer: ON Semiconductor; U/M: EA; Power_W: 0.55; Vz_V: 7.5; Value1: 0.55W; RJA_CperW: 226
D2 D4 = LTST-C190GKT: LED, Green, SMD; Manufacturer: Lite-On; Vf_V: 2.1; Value2: 2.1V; Io_A: 0.02; Power_TotalModule: 0.1; Value1: 0.1W; U/M: EA
D5-D10 = TPD1E10B06DPYR: ESD in 0402 Package with 10 pF Capacitance and 6 V Breakdown, 1 Channel, -40 to +125 degC, 2-pin X2SON (DPY), Green (RoHS & no Sb/Br); Manufacturer: Texas Instruments; Alternate Manufacturer: None; Alternate PartNumber: Equivalent; Breakdown Voltage(Min)(V): 6; Eco-Plan: TBD; IEC 61000-4-2 Air-Gap(+/- kV): 30; IO Capacitance(Typ)(pF): 10; SubFamily: ESD Solution
J1 = 1734035-2: Connector, Receptacle, Mini-USB Type B, R/A, Top Mount SMT; Manufacturer: TE Connectivity; SymbolCreator: A0412235; U/M: EA
J2 = SBH11-PBPC-D07-ST-BK: Header (shrouded), 100 mil, 7x2, Gold plated, TH; Manufacturer: Sullins Connector Solutions; SymbolCreator: a0412235; CompType: Connector; U/M: EA
J3 J5 = 90120-0122: Header, 100mil, 2x1, Tin plated, TH; Manufacturer: Molex; SymbolCreator: a0412235; U/M: EA
J4 = 0015912120: Header, 6x2, 100mil, SMT; Manufacturer: Molex; SymbolCreator: a0412235; U/M: EA
L2-L4 = BLM18SG331TN1D: 1.5A Ferrite Bead, 330 ohm @ 100MHz, SMD; Manufacturer: MuRata; Imax_A: 1.5; DCR_ohm: 0.07; Value1: 0.07 ohm; ZTyp@100MHz_Ohm: 330; U/M: EA
Q2 Q3 = BSS138: MOSFET, N-CH, 50V, 0.22A, SOT-23; Manufacturer: Fairchild Semiconductor; Alternate Manufacturer: None; U/M: EA; ChType: N; VdsMax_V: 50; Value1: 6 ohm; Rdson45_Ohm: 6; Value2: 1.7 nC; QgTyp_nC: 1.7; Vgs_V: 20; IdsMax_A: 0.22
R12 R23 = CRCW0603200RJNEA: RES, 200 ohm, 5%, 0.1W, 0603; Manufacturer: Vishay-Dale; CompType: Resistor; Value_Code: 200R; Tolerance_%: 5; Power_W: 0.1; VDC_V: 75; TempCo: 200 ppm/C; EIA_Code: E24; U/M: EA
R18 = CRCW04020000Z0ED: RES, 0 ohm, 5%, 0.063W, 0402; Manufacturer: Vishay-Dale; CompType: Resistor; Value_Code: 0000; Tolerance_%: 5; Power_W: 0.063; VDC_V: 50; TempCo: 200 ppm/C; EIA_Code: E24; U/M: EA
R19 R22 R26 = CRCW060347K5FKEA: RES, 47.5k ohm, 1%, 0.1W, 0603; Manufacturer: Vishay-Dale; CompType: Resistor; Res_ohm: 47500; Value_Code: 47k5; Tolerance_%: 1; Power_W: 0.1; VDC_V: 75; TempCo: 100 ppm/C; EIA_Code: E96; U/M: EA
R20 R21 = CRCW04024K99FKED: RES, 4.99k ohm, 1%, 0.063W, 0402; Manufacturer: Vishay-Dale; CompType: Resistor; Res_ohm: 4990; Value_Code: 4k99; Tolerance_%: 1; Power_W: 0.063; VDC_V: 50; TempCo: 100 ppm/C; EIA_Code: E96; U/M: EA
R24 = CRCW04021M00FKED: RES, 1.00Meg ohm, 1%, 0.063W, 0402; Manufacturer: Vishay-Dale; CompType: Resistor; Res_ohm: 1000000; Value_Code: 1M00; Tolerance_%: 1; Power_W: 0.063; VDC_V: 50; TempCo: 100 ppm/C; EIA_Code: E96; U/M: EA
R25 = CRCW04021K50FKED: RES, 1.50k ohm, 1%, 0.063W, 0402; Manufacturer: Vishay-Dale; CompType: Resistor; Res_ohm: 1500; Value_Code: 1k50; Tolerance_%: 1; Power_W: 0.063; VDC_V: 50; TempCo: 100 ppm/C; EIA_Code: E96; U/M: EA
S1-S3 = 4-1437565-1: Switch, Tactile, SPST-NO, 0.05A, 12V, SMT; Manufacturer: TE Connectivity; SymbolCreator: a0412235; VDC_V: 12; SwitchFunction: Off-Mom; PositionCount: 1; CurrentRating_mA: 50
SH-J1 SH-J2 = 2SN-BK-G: Shunt, 2mm, Gold plated, Black; Manufacturer: Samtec; Value: 1x2; Note: You can "mate" this to a header by matching the designator.  i.e. use SH-J3 for header J3
TP9 = 5003: Test Point, Miniature, Orange, TH; Manufacturer: Keystone; CompType: Test Point Loop; U/M: EA
TP10 = 5004: Test Point, Miniature, Yellow, TH; Manufacturer: Keystone; CompType: Test Point Loop; U/M: EA
TP13 TP15 TP16 = 5000: Test Point, Miniature, Red, TH; Manufacturer: Keystone; CompType: Test Point Loop; U/M: EA
TP14 = 5001: as TP1 on sheet ISE4012 sheet3
U2 = LP2985AIM5-3.3/NOPB: Micropower 150 mA Low-Noise Ultra Low-Dropout Regulator, 5-pin SOT-23, Pb-Free; Manufacturer: National Semiconductor; PackageTopMarking: L0RA*XTT; PowerWise: N; CompType: LDO IC
U3 = MSP430F5529IPN: Mixed Signal MicroController, PN0080A; Alternate Manufacturer: None; Manufacturer: Texas Instruments; ADC: 12-bit SAR; ADC Channels: 16; Brown Out Reset: Yes; DMA: 3; Eco-Plan: Green (RoHS & no Sb/Br); Flash(KB): 128; Frequency(MHz): 25; GPIO: 63; Multiplier: 32x32; SRAM(B): 8192; SubFamily: 5 Series; Timers - 16-bit: 4; USB: 1; USCI_A (UART/LIN/IrDA/SPI): 2; SymbolCreator: Altium/a0412235; CompType: IC; U/M: EA
U4 = TPD3E001DRLR: Low-Capacitance + / - 15 kV ESD-Protection Array for High-Speed Data Interfaces, 3 Channels, -40 to +85 degC, 5-pin SOT (DRL), Green (RoHS & no Sb/Br); Manufacturer: Texas Instruments; Alternate Manufacturer: None; Alternate PartNumber: Equivalent; Breakdown Voltage(Min)(V): 11; IEC 61000-4-2 Air-Gap(+/- kV): 15; IEC 61000-4-2 Contact(+/- kV): 8; IO Capacitance(Typ)(pF): 1.5; IO Leakage Current(nA): 1; SubFamily: ESD Solution; USB High Speed: TRUE
Y1 = ABMM-24.000MHZ-B2-T: Crystal, 24.000MHz, 18pF, SMD; Manufacturer: Abracon Corportation; SymbolCreator: a0412235; U/M: EA; TaMin_C: -20; TaMax_C: 70; Frequency Stability: ±50ppm

## Sheet ISE4012 sheet5.SchDoc
size 431 x 279 mm; Date: Not shown in title block; ApprovedBy: Not shown in title block; CheckedBy: Not shown in title block; Author: Not shown in title block; CompanyName: Not shown in title block; Engineer: Not shown in title block; Organization: Not shown in title block; Address1: Not shown in title block; Address2: Not shown in title block; Address3: Not shown in title block; Address4: Not shown in title block; DocumentNumber: 5; Revision: Use project parameter SCH_Rev; SheetNumber: 5; SheetTotal: 6; PageSetup: Record=PageOptions|CenterHorizontal=True|CenterVertical=True|PrintScale=0.96|XCorrection=1.00|YCorrection=1.00|PrintKind=0|BorderSize=5000000|LeftOffset=0|BottomOffset=0|Orientation=2|PaperLength=4318|PaperWidth=2794|Scale=100|PaperSource=15|PrintQuality=600|MediaType=1|DitherType=10|PaperKind=11x17|PrintScaleMode=1
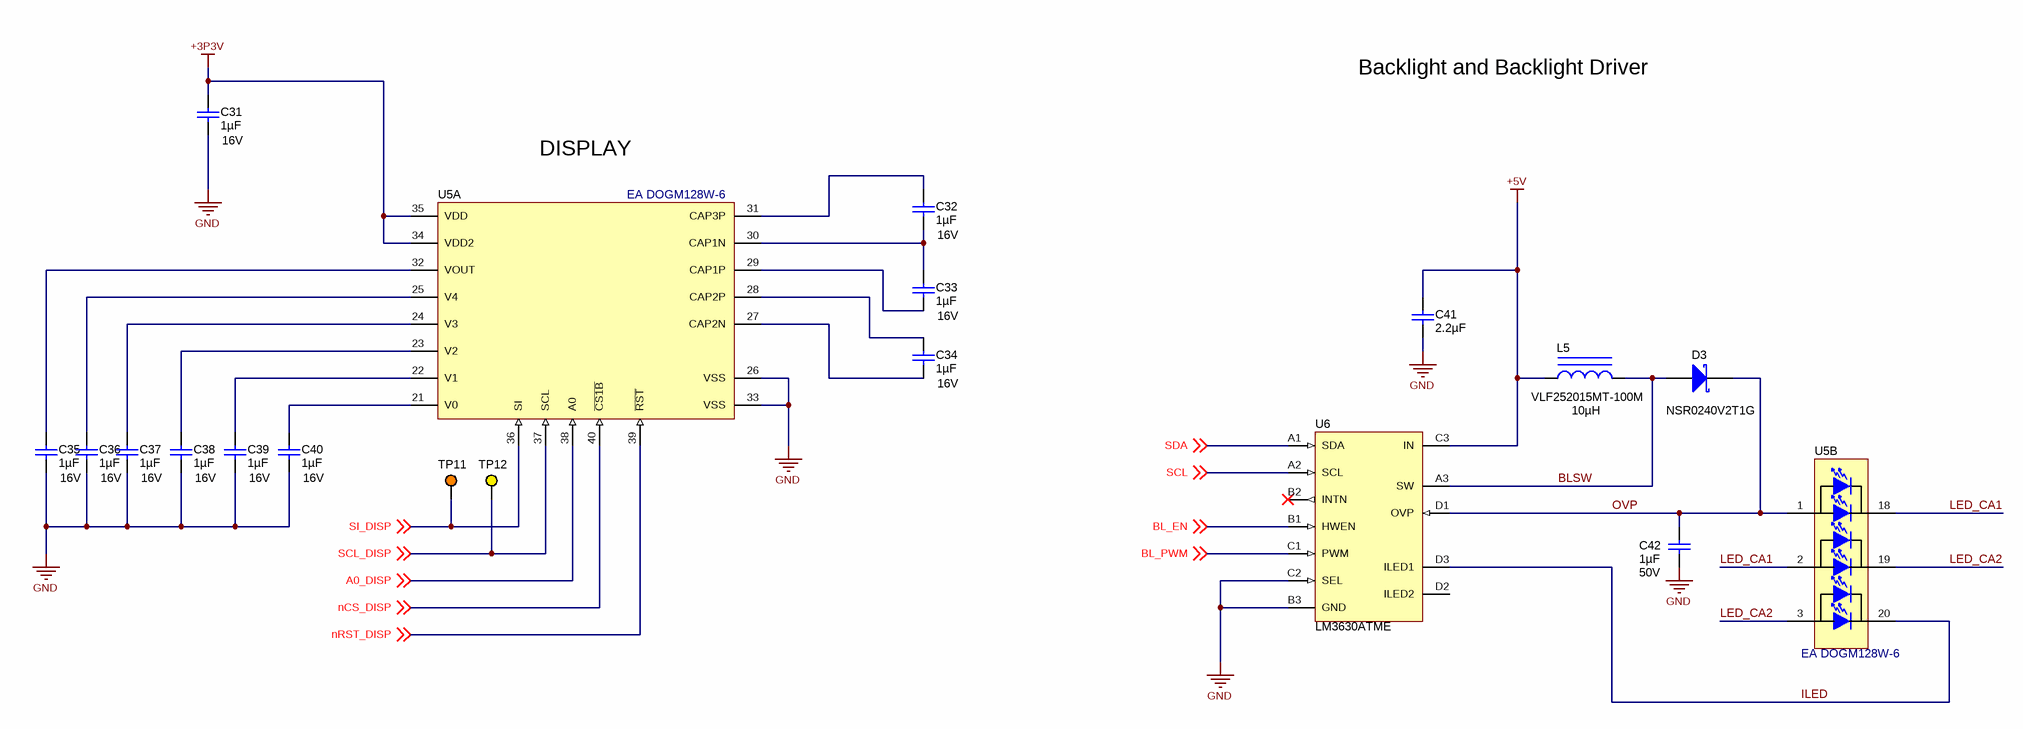
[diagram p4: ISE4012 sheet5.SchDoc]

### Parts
C31  ValueDisplayed: 1µF  Value2: 16V  [0603]  (hidden comment: C1608X7R1C105K)
C32  ValueDisplayed: 1µF  Value2: 16V  [0603]  (hidden comment: C1608X7R1C105K)
C33  ValueDisplayed: 1µF  Value2: 16V  [0603]  (hidden comment: C1608X7R1C105K)
C34  ValueDisplayed: 1µF  Value2: 16V  [0603]  (hidden comment: C1608X7R1C105K)
C35  ValueDisplayed: 1µF  Value2: 16V  [0603]  (hidden comment: C1608X7R1C105K)
C36  ValueDisplayed: 1µF  Value2: 16V  [0603]  (hidden comment: C1608X7R1C105K)
C37  ValueDisplayed: 1µF  Value2: 16V  [0603]  (hidden comment: C1608X7R1C105K)
C38  ValueDisplayed: 1µF  Value2: 16V  [0603]  (hidden comment: C1608X7R1C105K)
C39  ValueDisplayed: 1µF  Value2: 16V  [0603]  (hidden comment: C1608X7R1C105K)
C40  ValueDisplayed: 1µF  Value2: 16V  [0603]  (hidden comment: C1608X7R1C105K)
C41  ValueDisplayed: 2.2µF  [0603]  (hidden comment: C0603C225K8PACTU)
C42  ValueDisplayed: 1µF  Value2: 50V  [0805_HV]  (hidden comment: GRM21BR71H105KA12L)
D3  NSR0240V2T1G  [SOD-523]
L5  VLF252015MT-100M  ValueDisplayed: 10µH  [IND_VLF252015]
TP11  5003  [Keystone5003]  (value not drawn)
TP12  5004  [Keystone5004]  (value not drawn)
U5  EA DOGM128W-6  [LCD-MODULE_EA DOGM128W-6]  (parts A,B of 2)
U6  LM3630ATME  [YFQ0012AKAR]

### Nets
+3P3V: C31.1 U5.34(VDD2) U5.35(VDD)
+5V: C41.1 L5.1 U6.C3(IN)
GND: C31.2 C35.2 C36.2 C37.2 C38.2 C39.2 C40.2 C41.2 C42.2 U5.26(VSS) U5.33(VSS) U6.B3(GND) U6.C2(SEL)
A0_DISP: U5.38(A0) ; off-sheet A0_DISP
BL_EN: U6.B1(HWEN) ; off-sheet BL_EN
BL_PWM: U6.C1(PWM) ; off-sheet BL_PWM
BLSW: D3.2(A) L5.2 U6.A3(SW)
ILED: U5.20(K) U6.D3(ILED1)
LED_CA1: U5.2(A) U5.18(K)
LED_CA2: U5.3(A) U5.19(K)
nCS_DISP: U5.40(~{CS1B}) ; off-sheet nCS_DISP
nRST_DISP: U5.39(~{RST}) ; off-sheet nRST_DISP
OVP: C42.1 D3.1(K) U5.1(A) U6.D1(OVP)
SCL: U6.A2(SCL) ; off-sheet SCL
SCL_DISP: TP12.1 U5.37(SCL) ; off-sheet SCL_DISP
SDA: U6.A1(SDA) ; off-sheet SDA
SI_DISP: TP11.1 U5.36(SI) ; off-sheet SI_DISP
NetC32_1: C32.1 U5.31(CAP3P)
NetC32_2: C32.2 C33.1 U5.30(CAP1N)
NetC33_2: C33.2 U5.29(CAP1P)
NetC34_1: C34.1 U5.28(CAP2P)
NetC34_2: C34.2 U5.27(CAP2N)
NetC35_1: C35.1 U5.32(VOUT)
NetC36_1: C36.1 U5.25(V4)
NetC37_1: C37.1 U5.24(V3)
NetC38_1: C38.1 U5.23(V2)
NetC39_1: C39.1 U5.22(V1)
NetC40_1: C40.1 U5.21(V0)

Not connected (* = marked no-connect by the designer): U6 B2(INTN)* D2(ILED2)

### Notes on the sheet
- Backlight and Backlight Driver
- DISPLAY

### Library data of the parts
C31-C40 = C1608X7R1C105K: as C9 on sheet ISE4012 sheet3
C41 = C0603C225K8PACTU: CAP, CERM, 2.2uF, 10V, +/-10%, X5R, 0603; Manufacturer: Kemet; Polarized: N; CompType: Capacitor; U/M: EA; Cap_F: 0.0000022; Tolerance_%: 10; Value1: Unknown; TaMin_C: -55; TaMax_C: 85
C42 = GRM21BR71H105KA12L: CAP, CERM, 1uF, 50V, +/-10%, X7R, 0805; Manufacturer: MuRata; Polarized: N; CompType: Capacitor; U/M: EA; Cap_F: 0.000001; Tolerance_%: 10; Value1: Unknown; VDC_V: 50; TaMin_C: -55; TaMax_C: 125; Cap_Case: 0805
D3 = NSR0240V2T1G: Diode, Schottky, 40V, 0.25A, SOD-523; Manufacturer: ON Semiconductor; U/M: EA; Vf_V: 0.7; Value2: 0.7V; Io_A: 0.25; Vr_V: 40; TJmax_C: 150; RJC_CperW: 600
L5 = VLF252015MT-100M: Inductor, Shielded, Ferrite, 10uH, 0.47A, 0.24 ohm, SMD; Manufacturer: TDK; Ind_H: 10.0E-6; Imax_A: 0.47; Irms: 0.94A @ 40C rise; Isat: 0.47A @ 30% inductance drop; DCR_ohm: 0.24
TP11 = 5003: as TP9 on sheet ISE4012 sheet4
TP12 = 5004: as TP10 on sheet ISE4012 sheet4
U5 = EA DOGM128W-6: Module, 128x64-pixel graphics display; Manufacturer: Electronic Assembly; SymbolCreator: a0799628
U6 = LM3630ATME: LM3630A High-Efficiency Dual-String White LED Driver, YFQ0012AKAR; Alternate Manufacturer: None; Manufacturer: Texas Instruments; SymbolCreator: a0411947; CompType: IC; U/M: EA

## Sheet ISE4012 Sheet 6.SchDoc
size 431 x 279 mm; Date: Not shown in title block; ApprovedBy: Not shown in title block; CheckedBy: Not shown in title block; Author: Not shown in title block; CompanyName: Not shown in title block; Engineer: Not shown in title block; Organization: Not shown in title block; Address1: Not shown in title block; Address2: Not shown in title block; Address3: Not shown in title block; Address4: Not shown in title block; DocumentNumber: 6; Revision: Use project parameter SCH_Rev; SheetNumber: 6; SheetTotal: 6; PageSetup: Record=PageOptions|CenterHorizontal=True|CenterVertical=True|PrintScale=1.00|XCorrection=1.00|YCorrection=1.00|PrintKind=0|BorderSize=5000000|LeftOffset=0|BottomOffset=0|Orientation=2|PaperLength=1000|PaperWidth=1000|Scale=100|PaperSource=15|PrintQuality=600|MediaType=1|DitherType=10|PaperKind=Letter|PrintScaleMode=1
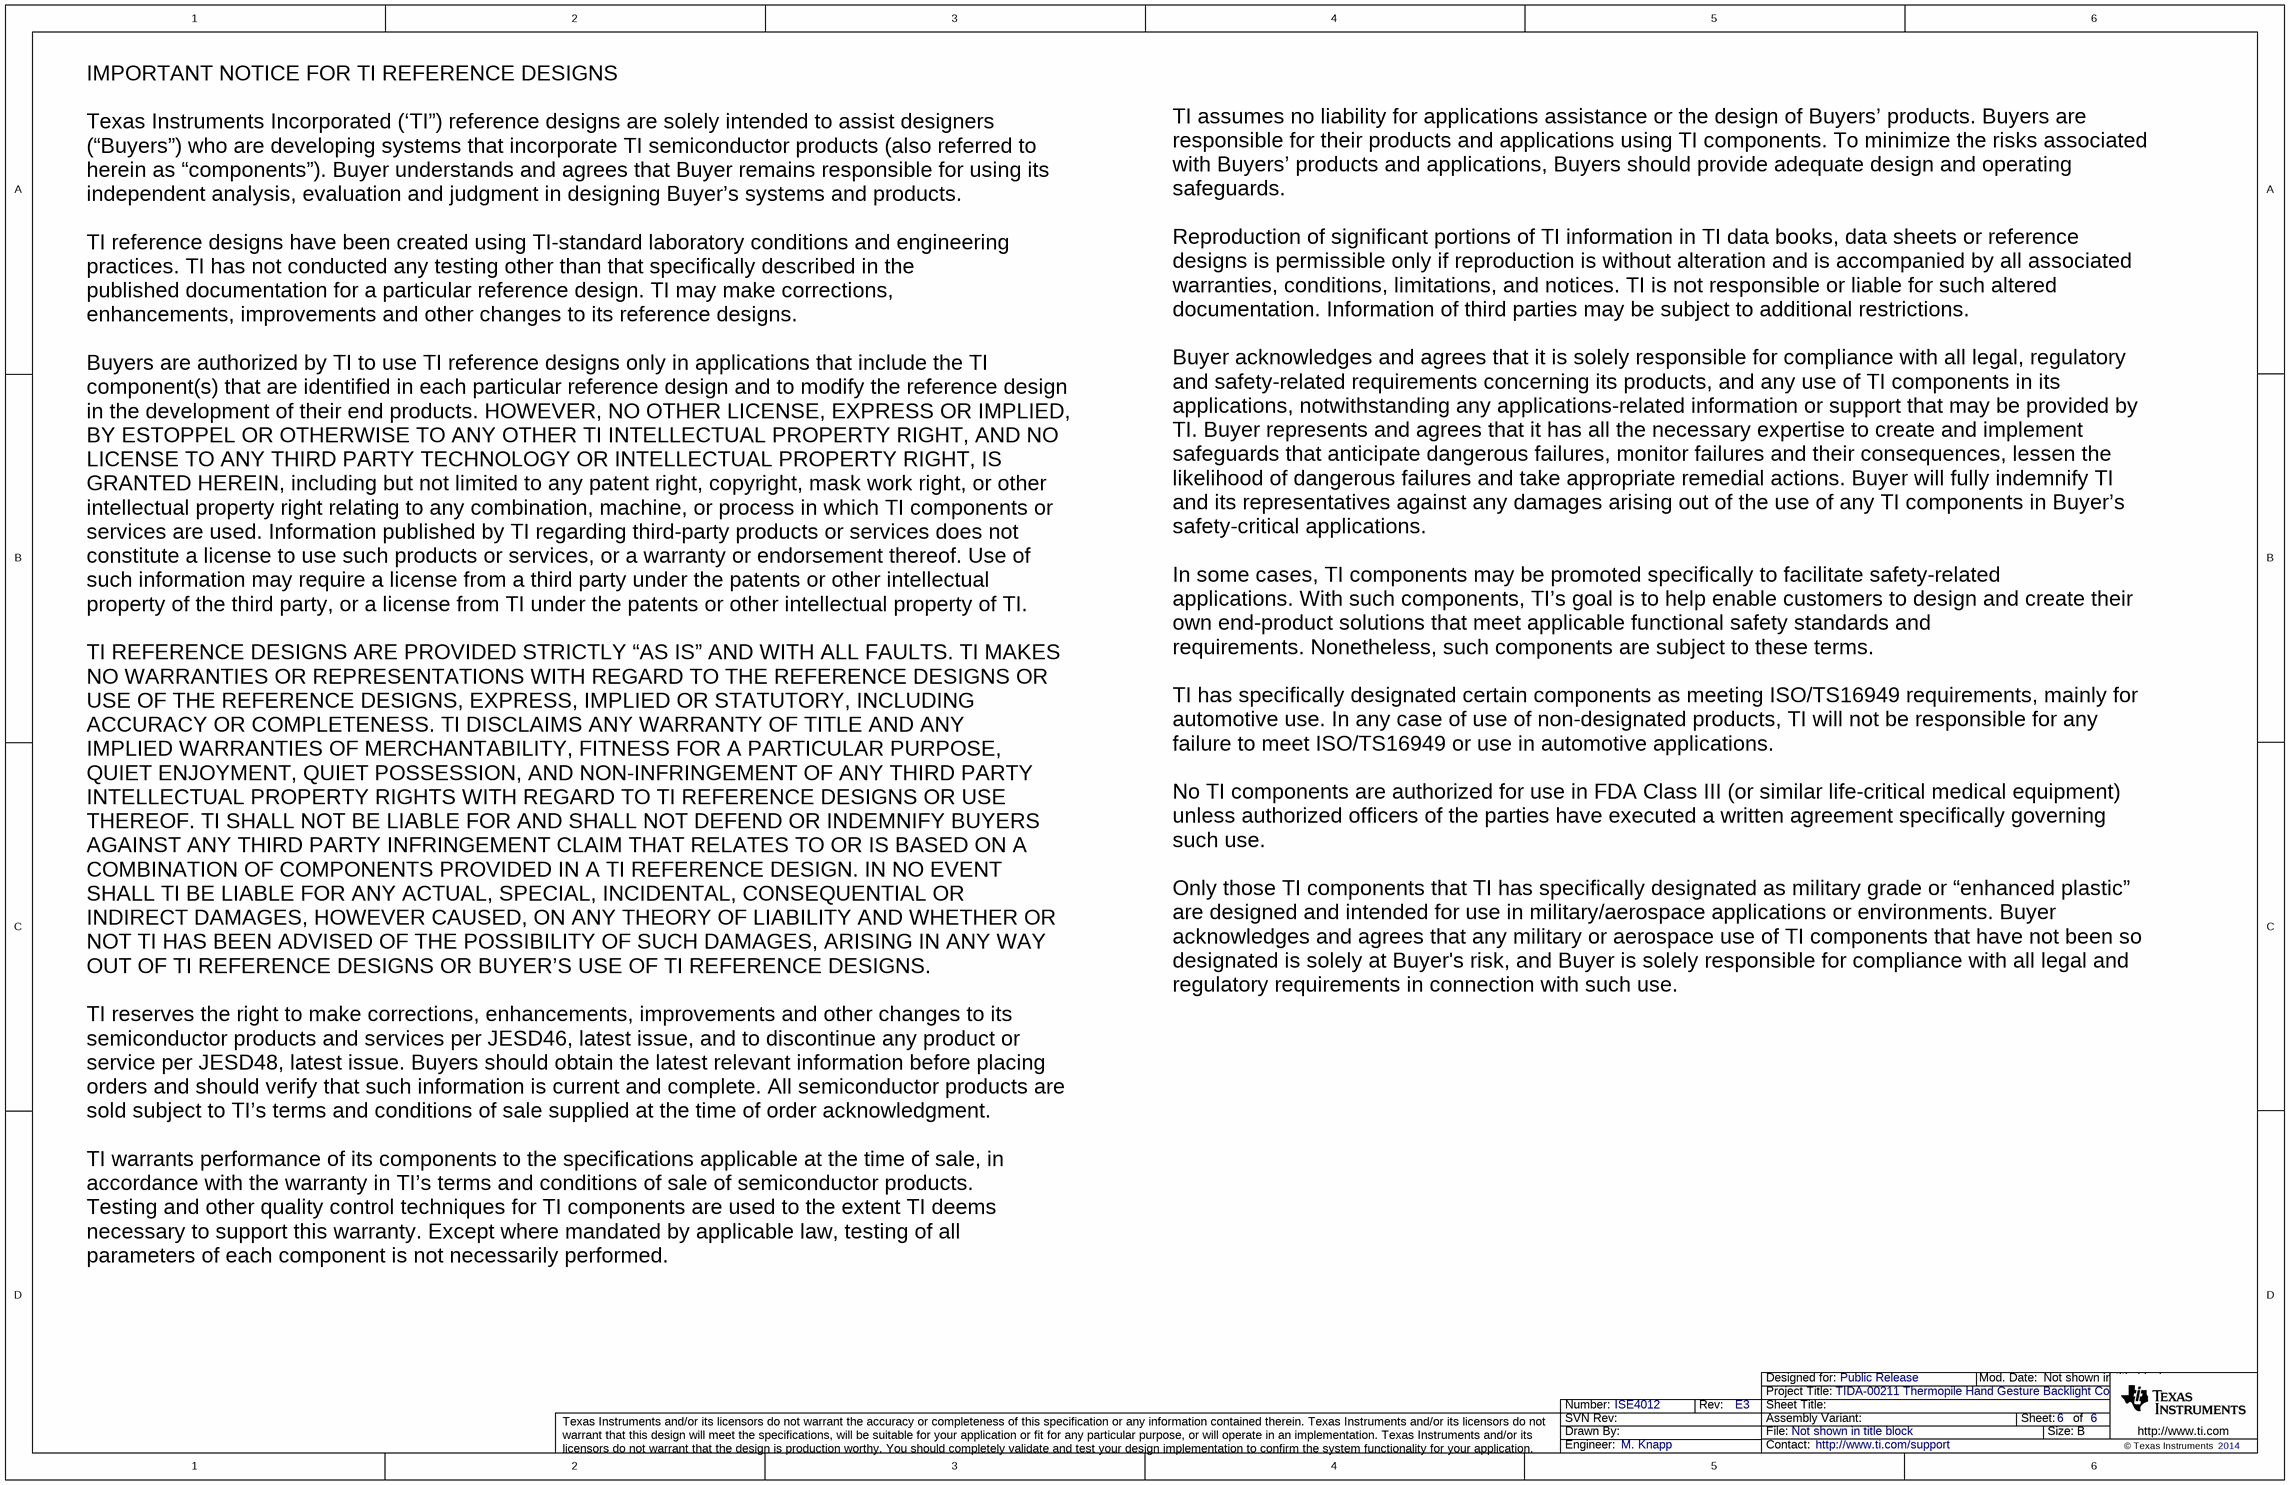
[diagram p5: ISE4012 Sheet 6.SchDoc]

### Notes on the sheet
- IMPORTANT NOTICE FOR TI REFERENCE DESIGNS
  Texas Instruments Incorporated (‘TI”) reference designs are solely intended to assist designers
  (“Buyers”) who are developing systems that incorporate TI semiconductor products (also referred to
  herein as “components”). Buyer understands and agrees that Buyer remains responsible for using its
  independent analysis, evaluation and judgment in designing Buyer’s systems and products.
  TI reference designs have been created using TI-standard laboratory conditions and engineering
  practices. TI has not conducted any testing other than that specifically described in the
  published documentation for a particular reference design. TI may make corrections,
  enhancements, improvements and other changes to its reference designs.
  Buyers are authorized by TI to use TI reference designs only in applications that include the TI
  component(s) that are identified in each particular reference design and to modify the reference design
  in the development of their end products. HOWEVER, NO OTHER LICENSE, EXPRESS OR IMPLIED,
  BY ESTOPPEL OR OTHERWISE TO ANY OTHER TI INTELLECTUAL PROPERTY RIGHT, AND NO
  LICENSE TO ANY THIRD PARTY TECHNOLOGY OR INTELLECTUAL PROPERTY RIGHT, IS
  GRANTED HEREIN, including but not limited to any patent right, copyright, mask work right, or other
  intellectual property right relating to any combination, machine, or process in which TI components or
  services are used. Information published by TI regarding third-party products or services does not
  constitute a license to use such products or services, or a warranty or endorsement thereof. Use of
  such information may require a license from a third party under the patents or other intellectual
  property of the third party, or a license from TI under the patents or other intellectual property of TI.
  TI REFERENCE DESIGNS ARE PROVIDED STRICTLY “AS IS” AND WITH ALL FAULTS. TI MAKES
  NO WARRANTIES OR REPRESENTATIONS WITH REGARD TO THE REFERENCE DESIGNS OR
  USE OF THE REFERENCE DESIGNS, EXPRESS, IMPLIED OR STATUTORY, INCLUDING
  ACCURACY OR COMPLETENESS. TI DISCLAIMS ANY WARRANTY OF TITLE AND ANY
  IMPLIED WARRANTIES OF MERCHANTABILITY, FITNESS FOR A PARTICULAR PURPOSE,
  QUIET ENJOYMENT, QUIET POSSESSION, AND NON-INFRINGEMENT OF ANY THIRD PARTY
  INTELLECTUAL PROPERTY RIGHTS WITH REGARD TO TI REFERENCE DESIGNS OR USE
  THEREOF. TI SHALL NOT BE LIABLE FOR AND SHALL NOT DEFEND OR INDEMNIFY BUYERS
  AGAINST ANY THIRD PARTY INFRINGEMENT CLAIM THAT RELATES TO OR IS BASED ON A
  COMBINATION OF COMPONENTS PROVIDED IN A TI REFERENCE DESIGN. IN NO EVENT
  SHALL TI BE LIABLE FOR ANY ACTUAL, SPECIAL, INCIDENTAL, CONSEQUENTIAL OR
  INDIRECT DAMAGES, HOWEVER CAUSED, ON ANY THEORY OF LIABILITY AND WHETHER OR
  NOT TI HAS BEEN ADVISED OF THE POSSIBILITY OF SUCH DAMAGES, ARISING IN ANY WAY
  OUT OF TI REFERENCE DESIGNS OR BUYER’S USE OF TI REFERENCE DESIGNS.
  TI reserves the right to make corrections, enhancements, improvements and other changes to its
  semiconductor products and services per JESD46, latest issue, and to discontinue any product or
  service per JESD48, latest issue. Buyers should obtain the latest relevant information before placing
  orders and should verify that such information is current and complete. All semiconductor products are
  sold subject to TI’s terms and conditions of sale supplied at the time of order acknowledgment.
  TI warrants performance of its components to the specifications applicable at the time of sale, in
  accordance with the warranty in TI’s terms and conditions of sale of semiconductor products.
  Testing and other quality control techniques for TI components are used to the extent TI deems
  necessary to support this warranty. Except where mandated by applicable law, testing of all
  parameters of each component is not necessarily performed.
- TI assumes no liability for applications assistance or the design of Buyers’ products. Buyers are
  responsible for their products and applications using TI components. To minimize the risks associated
  with Buyers’ products and applications, Buyers should provide adequate design and operating
  safeguards.
  Reproduction of significant portions of TI information in TI data books, data sheets or reference
  designs is permissible only if reproduction is without alteration and is accompanied by all associated
  warranties, conditions, limitations, and notices. TI is not responsible or liable for such altered
  documentation. Information of third parties may be subject to additional restrictions.
  Buyer acknowledges and agrees that it is solely responsible for compliance with all legal, regulatory
  and safety-related requirements concerning its products, and any use of TI components in its
  applications, notwithstanding any applications-related information or support that may be provided by
  TI. Buyer represents and agrees that it has all the necessary expertise to create and implement
  safeguards that anticipate dangerous failures, monitor failures and their consequences, lessen the
  likelihood of dangerous failures and take appropriate remedial actions. Buyer will fully indemnify TI
  and its representatives against any damages arising out of the use of any TI components in Buyer’s
  safety-critical applications.
  In some cases, TI components may be promoted specifically to facilitate safety-related
  applications. With such components, TI’s goal is to help enable customers to design and create their
  own end-product solutions that meet applicable functional safety standards and
  requirements. Nonetheless, such components are subject to these terms.
  TI has specifically designated certain components as meeting ISO/TS16949 requirements, mainly for
  automotive use. In any case of use of non-designated products, TI will not be responsible for any
  failure to meet ISO/TS16949 or use in automotive applications.
  No TI components are authorized for use in FDA Class III (or similar life-critical medical equipment)
  unless authorized officers of the parties have executed a written agreement specifically governing
  such use.
  Only those TI components that TI has specifically designated as military grade or “enhanced plastic”
  are designed and intended for use in military/aerospace applications or environments. Buyer
  acknowledges and agrees that any military or aerospace use of TI components that have not been so
  designated is solely at Buyer's risk, and Buyer is solely responsible for compliance with all legal and
  regulatory requirements in connection with such use.

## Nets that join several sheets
+3P3V: ISE4012 sheet3 (R1.2 R13.2 R14.2), ISE4012 sheet4 (16 pins), ISE4012 sheet5 (C31.1 U5.34 U5.35)
+5V: ISE4012 sheet4 (C15.1 L2.2), ISE4012 sheet5 (C41.1 L5.1 U6.C3)
AVCC: ISE4012 sheet3 (5 pins), ISE4012 sheet4 (C28.1 C29.1 L4.2 U3.11)
GND: ISE4012 sheet3 (20 pins), ISE4012 sheet4 (51 pins), ISE4012 sheet5 (13 pins)
A0_DISP: ISE4012 sheet4 (U3.34), ISE4012 sheet5 (U5.38)
ADC_A0: ISE4012 sheet3 (R3.1 TS1.2), ISE4012 sheet4 (U3.77)
ADC_A2: ISE4012 sheet3 (C11.1 Q1.2 R16.2), ISE4012 sheet4 (U3.79)
BL_EN: ISE4012 sheet4 (U3.31), ISE4012 sheet5 (U6.B1)
BL_PWM: ISE4012 sheet4 (U3.30), ISE4012 sheet5 (U6.C1)
CS_AFE: ISE4012 sheet3 (U1.15), ISE4012 sheet4 (U3.29)
DRDYB: ISE4012 sheet3 (R10.2), ISE4012 sheet4 (U3.33)
nCS_DISP: ISE4012 sheet4 (U3.39), ISE4012 sheet5 (U5.40)
nPWDNB: ISE4012 sheet3 (R13.1 U1.9), ISE4012 sheet4 (U3.6)
nRST_DISP: ISE4012 sheet4 (U3.35), ISE4012 sheet5 (U5.39)
nRSTB: ISE4012 sheet3 (R14.1 U1.10), ISE4012 sheet4 (U3.5)
SCL: ISE4012 sheet4 (R21.1 TP10.1 U3.38), ISE4012 sheet5 (U6.A2)
SCL_DISP: ISE4012 sheet4 (U3.36), ISE4012 sheet5 (TP12.1 U5.37)
SCLK_AFE: ISE4012 sheet3 (U1.17), ISE4012 sheet4 (U3.45)
SDA: ISE4012 sheet4 (R20.1 TP9.1 U3.37), ISE4012 sheet5 (U6.A1)
SDI_AFE: ISE4012 sheet3 (U1.14), ISE4012 sheet4 (U3.51)
SDO_AFE: ISE4012 sheet3 (R11.2), ISE4012 sheet4 (U3.52)
SI_DISP: ISE4012 sheet4 (U3.40), ISE4012 sheet5 (TP11.1 U5.36)
SYNC: ISE4012 sheet3 (U1.11), ISE4012 sheet4 (U3.4)
XCLK: ISE4012 sheet3 (U1.12), ISE4012 sheet4 (U3.23)

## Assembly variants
001: not fitted C11 C43 FID1 FID2 FID3 Q1 R16 TP5 TP6 TP7 TP8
